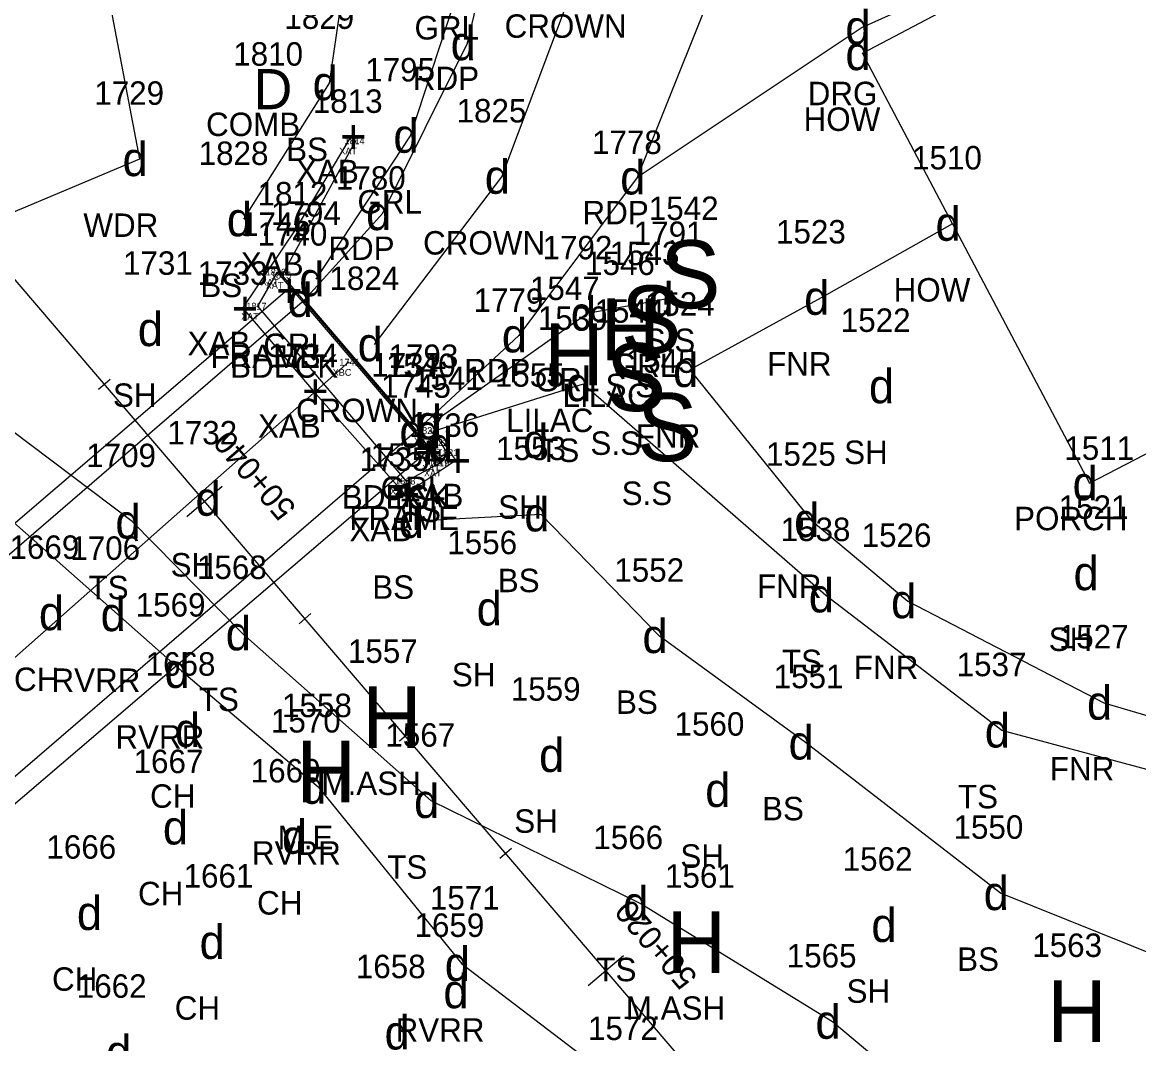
# Model space of a CAD drawing. Extents: x 461160 to 461373, y 202903 to 203086.
# Drawn here: x 461314.15 to 461350.31, y 202961.57 to 202994.66 of the extents above; entities that cross this region are included whole.
import ezdxf

# ---------------------------------------------------------------- set-up
doc = ezdxf.new("R2010")
doc.units = 0
for name, color, linetype in [('Level 11', 7, 'Continuous'), ('Level 12', 7, 'Continuous'), ('Level 13', 7, 'Continuous'), ('Level 14', 7, 'Continuous'), ('Level 15', 7, 'Continuous'), ('Level 17', 7, 'Continuous'), ('Level 34', 7, 'Continuous'), ('Level 35', 7, 'Continuous'), ('Level 37', 7, 'Continuous'), ('Level 46', 7, 'Continuous'), ('Level 47', 7, 'Continuous'), ('Level 48', 7, 'Continuous'), ('Level 49', 7, 'Continuous')]:
    doc.layers.add(name, color=color, linetype=linetype)

msp = doc.modelspace()

# ---------------------------------------------------------------- linework, layer by layer
at = {"layer": 'Level 11'}
for points in [[(461368.16, 202993.988), (461361.614, 202999.669), (461352.956, 203006.007), (461341.424, 203009.197), (461337.518, 203007.355), (461337.431, 203004.112), (461337.186, 202997.424), (461334.068, 202989.63), (461330.234, 202984.513), (461326.916, 202981.421), (461323.296, 202985.661), (461325.835, 202988.474), (461328.575, 202993.98), (461329.756, 202998.988), (461329.989, 203003.994), (461337.431, 203004.112), (461329.989, 203003.994)], [(461337.431, 203004.112), (461339.381, 203001.223), (461342.793, 203002.894), (461345.883, 202999.616), (461347.736, 203000.184), (461348.888, 202997.876), (461341.361, 202994.491), (461334.068, 202989.63)]]:
    msp.add_lwpolyline(points, dxfattribs=at)
at = {"layer": 'Level 12'}
msp.add_line((461346.056, 202948.738), (461294.056, 203009.532), dxfattribs=at)
for points in [[(461323.672, 202986.332), (461326.722, 202990.981), (461328.569, 202996.619), (461329.316, 203001.28), (461328.204, 203004.939)], [(461344.281, 202988.129), (461340.027, 202985.73), (461335.779, 202983.392), (461339.702, 202978.527), (461342.84, 202975.899), (461349.186, 202972.612), (461353.842, 202971.233), (461355.83, 202970.143), (461358.135, 202966.469)], [(461334.989, 202985.682), (461332.465, 202985.218), (461327.476, 202981.698)]]:
    msp.add_lwpolyline(points, dxfattribs=at)
at = {"layer": 'Level 13'}
for points in [[(461344.281, 202988.129), (461341.364, 202993.658), (461347.97, 202997.141), (461350.021, 202998.196), (461353.693, 202991.517), (461352.33, 202990.757), (461354.403, 202986.654)], [(461344.281, 202988.129), (461348.72, 202979.72), (461356.092, 202983.553), (461354.403, 202986.654)], [(461316.616, 202982.772), (461316.996, 202983.097)], [(461319.486, 202978.648), (461320.626, 202979.623)], [(461323.116, 202975.173), (461323.496, 202975.498)], [(461326.366, 202971.373), (461326.746, 202971.698)], [(461329.616, 202967.574), (461329.996, 202967.899)], [(461332.486, 202963.449), (461333.626, 202964.424)]]:
    msp.add_lwpolyline(points, dxfattribs=at)
at = {"layer": 'Level 14'}
msp.add_lwpolyline([(461301.65, 202990.994), (461304.551, 202996.947), (461311.823, 203001.37), (461316.945, 203004), (461316.225, 202999.291), (461317.949, 202990.224), (461310.29, 202987.008), (461301.65, 202990.994)], dxfattribs=at)
at = {"layer": 'Level 17'}
for points in [[(461271.342, 203006.356), (461278.053, 203003.256), (461286.412, 202998.583), (461294.243, 202992.971), (461302.269, 202987.612), (461311.447, 202980.59), (461317.239, 202975.481), (461319.309, 202973.643)], [(461319.309, 202973.643), (461323.731, 202969.886), (461328.385, 202964.15), (461333.938, 202959.923), (461341.989, 202956.284)]]:
    msp.add_lwpolyline(points, dxfattribs=at)
at = {"layer": 'Level 34'}
for points in [[(461326.916, 202981.421), (461313.074, 202969.494), (461299.278, 202957.624), (461295.638, 202961.869), (461309.508, 202973.783), (461323.296, 202985.661), (461326.916, 202981.421)], [(461324.72, 202983.644), (461311.442, 202971.896), (461297.739, 202960.242)]]:
    msp.add_lwpolyline(points, dxfattribs=at)
at = {"layer": 'Level 35'}
for points in [[(461321.296, 202985.391), (461323.019, 202987.964), (461324.808, 202990.962)], [(461324.947, 202990.818), (461322.567, 202986.463), (461322.409, 202986.565), (461321.769, 202985.459), (461326.591, 202979.793), (461327.688, 202980.382), (461327.637, 202980.538), (461327.918, 202980.713), (461327.71, 202981.041), (461327.363, 202981.429)], [(461322.409, 202986.565), (461327.688, 202980.382)], [(461327.637, 202980.538), (461322.567, 202986.463)], [(461321.296, 202985.391), (461323.574, 202982.72), (461326.539, 202979.364), (461328.193, 202980.466), (461327.836, 202980.984)]]:
    msp.add_lwpolyline(points, dxfattribs=at)
at = {"layer": 'Level 37'}
for points in [[(461322.735, 202985.975), (461295.405, 202962.57)], [(461299.888, 202957.36), (461327.236, 202980.731)]]:
    msp.add_lwpolyline(points, dxfattribs=at)
at = {"layer": 'Level 48'}
for points in [[(461321.327, 202988.274), (461324.106, 202992.683), (461325.466, 203002.03), (461321.733, 203002.708), (461316.945, 203004), (461321.225, 203006.69), (461324.085, 203007.39), (461327.398, 203011.243), (461327.047, 203014.732), (461324.41, 203015.108), (461324.41, 203015.108), (461321.477, 203013.865), (461317.057, 203013.221), (461311.718, 203019.474), (461304.97, 203028.576), (461302.488, 203033.292)], [(461321.327, 202988.274), (461324.106, 202992.683), (461325.466, 203002.03), (461321.733, 203002.708), (461316.945, 203004), (461321.225, 203006.69), (461324.085, 203007.39), (461327.398, 203011.243), (461327.047, 203014.732), (461324.41, 203015.108), (461324.41, 203015.108), (461321.477, 203013.865), (461317.057, 203013.221), (461311.718, 203019.474), (461304.97, 203028.576), (461302.488, 203033.292)], [(461321.29, 202974.86), (461317.717, 202978.484), (461312.473, 202982.423), (461305.824, 202987.874), (461301.65, 202990.994), (461300.034, 202993.51), (461304.787, 202998.277), (461312.691, 203003.124), (461318.698, 203006.786), (461322.707, 203009.684), (461325.345, 203012.481), (461324.782, 203012.846), (461322.016, 203009.952), (461316.942, 203006.65), (461311.004, 203002.871), (461303.318, 202997.851), (461297.451, 202992.823)], [(461321.29, 202974.86), (461317.717, 202978.484), (461312.473, 202982.423), (461305.824, 202987.874), (461301.65, 202990.994), (461300.034, 202993.51), (461304.787, 202998.277), (461312.691, 203003.124), (461318.698, 203006.786), (461322.707, 203009.684), (461325.345, 203012.481), (461324.782, 203012.846), (461322.016, 203009.952), (461316.942, 203006.65), (461311.004, 203002.871), (461303.318, 202997.851), (461297.451, 202992.823)], [(461325.564, 202984.223), (461329.682, 202989.652), (461332.323, 202996.674), (461333.208, 203003.38)], [(461357.687, 202965.645), (461352.427, 202969.949), (461345.877, 202971.711), (461340.176, 202976.089), (461332.316, 202982.931), (461327.452, 202981.402), (461327.836, 202980.984)], [(461357.687, 202965.645), (461352.427, 202969.949), (461345.877, 202971.711), (461340.176, 202976.089), (461332.316, 202982.931), (461327.452, 202981.402), (461327.836, 202980.984)], [(461352.229, 202963.871), (461345.84, 202966.444), (461339.521, 202971.322), (461334.79, 202974.771), (461330.961, 202978.713), (461326.896, 202978.498)], [(461352.229, 202963.871), (461345.84, 202966.444), (461339.521, 202971.322), (461334.79, 202974.771), (461330.961, 202978.713), (461326.896, 202978.498)], [(461344.812, 202958.571), (461340.392, 202962.274), (461334.167, 202966.108), (461327.392, 202969.428), (461321.29, 202974.86)], [(461344.812, 202958.571), (461340.392, 202962.274), (461334.167, 202966.108), (461327.392, 202969.428), (461321.29, 202974.86)]]:
    msp.add_lwpolyline(points, dxfattribs=at)

# ---------------------------------------------------------------- texts
at = {"layer": 'Level 13'}
for s, p in [('50+040', (461323.056, 202978.935)), ('50+020', (461336.056, 202963.737))]:
    msp.add_text(s, height=0.75, rotation=130.5419, dxfattribs=at).set_placement(p)
at = {"layer": 'Level 14'}
for s, height, p in [('S', 2.2, (461334.807, 202985.392)), ('S', 2.2, (461333.539, 202983.929)), ('H', 2, (461332.882, 202983.71)), ('H', 2, (461331.056, 202982.9)), ('S', 2.2, (461333.048, 202982.062)), ('S', 2.2, (461334.06, 202980.439)), ('H', 2, (461325.162, 202971.142)), ('H', 2, (461323.028, 202969.384)), ('H', 2, (461335.018, 202963.858)), ('H', 2, (461347.345, 202961.615))]:
    msp.add_text(s, height=height, dxfattribs=at).set_placement(p)
at = {"layer": 'Level 15'}
msp.add_text('D', height=1.3, dxfattribs=at).set_placement((461321.644, 202991.841))
at = {"layer": 'Level 46'}
for s, height, p in [(' GRL  ', 0.76, (461326.574, 202994.099)), (' CROWN  ', 0.76, (461329.493, 202994.154)), (' RDP  ', 0.76, (461326.523, 202992.46)), (' DRG  ', 0.76, (461339.309, 202991.971)), (' HOW  ', 0.76, (461339.177, 202991.138)), (' COMB  ', 0.76, (461319.823, 202990.971)), (' BS  ', 0.76, (461322.416, 202990.163)), (' XAT  ', 0.22, (461324.338, 202990.378)), (' XAB  ', 0.76, (461322.738, 202989.442)), (' GRL  ', 0.76, (461324.727, 202988.461)), (' RDP  ', 0.76, (461332.016, 202988.11)), (' WDR  ', 0.76, (461315.849, 202987.704)), (' CROWN  ', 0.76, (461326.852, 202987.132)), (' RDP  ', 0.76, (461323.783, 202986.954)), (' XAB  ', 0.76, (461320.949, 202986.444)), (' BS  ', 0.76, (461319.637, 202985.754)), (' XAT  ', 0.22, (461321.8, 202986.125)), (' XAT  ', 0.22, (461321.958, 202986.023)), (' HOW  ', 0.76, (461342.094, 202985.609)), (' XAT  ', 0.22, (461321.16, 202985.019)), (' XAB  ', 0.76, (461319.226, 202983.871)), (' GRL  ', 0.76, (461321.677, 202983.812)), (' S.S  ', 0.76, (461334.031, 202983.972)), (' FRAME  ', 0.76, (461319.962, 202983.455)), (' BDECK  ', 0.76, (461320.601, 202983.141)), (' GRL  ', 0.76, (461332.994, 202983.162)), (' FNR  ', 0.76, (461337.993, 202983.21)), (' RDP  ', 0.76, (461328.182, 202982.993)), (' XBC  ', 0.22, (461324.125, 202983.204)), (' GRL  ', 0.76, (461330.47, 202982.698)), (' S.S  ', 0.76, (461332.763, 202982.509)), (' SH  ', 0.76, (461316.808, 202982.196)), (' LILAC  ', 0.76, (461331.369, 202982.19)), (' CROWN  ', 0.76, (461322.734, 202981.703)), (' LILAC  ', 0.76, (461329.543, 202981.38)), (' XAB  ', 0.76, (461321.504, 202981.2)), (' S.S  ', 0.76, (461332.272, 202980.642)), (' FNR  ', 0.76, (461333.745, 202980.872)), (' XAT  ', 0.22, (461326.754, 202980.989)), (' TS  ', 0.76, (461330.614, 202980.411)), (' SH  ', 0.76, (461340.489, 202980.346)), (' XAT  ', 0.22, (461327.101, 202980.601)), (' XAT  ', 0.22, (461327.028, 202980.098)), (' XAT  ', 0.22, (461327.309, 202980.273)), (' GRL  ', 0.76, (461325.481, 202979.178)), (' XAT  ', 0.22, (461327.079, 202979.942)), (' BDECK  ', 0.76, (461324.221, 202978.901)), (' TS  ', 0.76, (461325.75, 202978.882)), (' XAT  ', 0.22, (461325.982, 202979.353)), (' XAB  ', 0.76, (461326.123, 202978.946)), (' S.S  ', 0.76, (461333.284, 202979.019)), (' TS  ', 0.76, (461326.134, 202978.464)), (' SH  ', 0.76, (461329.284, 202978.57)), (' FRAME  ', 0.76, (461324.463, 202978.211)), (' PORCH  ', 0.76, (461345.995, 202978.2)), (' XAB  ', 0.76, (461324.469, 202977.844)), (' SH  ', 0.76, (461318.676, 202976.7)), (' TS  ', 0.76, (461316.015, 202975.964)), (' BS  ', 0.76, (461325.206, 202975.978)), (' BS  ', 0.76, (461329.271, 202976.193)), (' FNR  ', 0.76, (461337.668, 202976.007)), (' SH  ', 0.76, (461347.115, 202974.288)), (' TS  ', 0.76, (461338.474, 202973.569)), (' FNR  ', 0.76, (461340.806, 202973.379)), (' CH  ', 0.76, (461313.604, 202972.992)), (' SH  ', 0.76, (461327.783, 202973.144)), (' RVRR  ', 0.76, (461314.816, 202972.961)), (' TS  ', 0.76, (461319.588, 202972.34)), (' BS  ', 0.76, (461333.1, 202972.251)), (' RVRR  ', 0.76, (461316.886, 202971.123)), (' FNR  ', 0.76, (461347.152, 202970.092)), (' M.ASH  ', 0.76, (461323.562, 202969.622)), (' CH  ', 0.76, (461318.01, 202969.208)), (' TS  ', 0.76, (461344.175, 202969.191)), (' BS  ', 0.76, (461337.831, 202968.802)), (' SH  ', 0.76, (461329.805, 202968.398)), (' M.E  ', 0.76, (461322.14, 202967.864)), (' RVRR  ', 0.76, (461321.308, 202967.366)), (' SH  ', 0.76, (461335.186, 202967.264)), (' TS  ', 0.76, (461325.69, 202966.908)), (' CH  ', 0.76, (461317.62, 202966.05)), (' CH  ', 0.76, (461321.476, 202965.748)), (' BS  ', 0.76, (461344.15, 202963.924)), (' TS  ', 0.76, (461332.465, 202963.588)), (' CH  ', 0.76, (461314.835, 202963.279)), (' SH  ', 0.76, (461340.568, 202962.889)), (' CH  ', 0.76, (461318.808, 202962.342)), (' M.ASH  ', 0.76, (461333.418, 202962.338)), (' RVRR  ', 0.76, (461325.962, 202961.63))]:
    msp.add_text(s, height=height, dxfattribs=at).set_placement(p)
at = {"layer": 'Level 47'}
for s, height, p in [('d', 1.1, (461340.811, 202993.941)), ('d', 1.1, (461328.025, 202993.43)), ('d', 1.1, (461340.814, 202993.108)), ('d', 1.1, (461323.556, 202992.133)), ('d', 1.1, (461326.172, 202990.431)), ('+', 1.1, (461324.449, 202990.412)), ('d', 1.1, (461317.399, 202989.674)), ('+', 0.15, (461324.898, 202990.743)), ('d', 1.1, (461329.132, 202989.102)), ('d', 1.1, (461333.518, 202989.08)), ('d', 1.1, (461325.285, 202987.924)), ('d', 1.1, (461320.777, 202987.724)), ('d', 1.1, (461343.731, 202987.579)), ('+', 1.1, (461322.66, 202987.414)), ('d', 1.1, (461323.122, 202985.782)), ('+', 0.15, (461322.36, 202986.49)), ('+', 0.15, (461322.518, 202986.388)), ('+', 1.1, (461322.376, 202985.425)), ('d', 1.1, (461322.746, 202985.111)), ('d', 1.1, (461334.439, 202985.132)), ('d', 1.1, (461339.477, 202985.18)), ('+', 1.1, (461320.937, 202984.841)), ('d', 1.1, (461331.915, 202984.668)), ('d', 1.1, (461317.894, 202984.166)), ('+', 0.15, (461321.72, 202985.384)), ('d', 1.1, (461329.684, 202983.963)), ('d', 1.1, (461325.014, 202983.673)), ('d', 1.1, (461335.229, 202982.842)), ('+', 0.15, (461324.671, 202983.569)), ('d', 1.1, (461331.766, 202982.381)), ('d', 1.1, (461341.575, 202982.316)), ('+', 1.1, (461323.215, 202982.17)), ('d', 1.1, (461326.926, 202981.148)), ('d', 1.1, (461326.366, 202980.871)), ('d', 1.1, (461326.902, 202980.852)), ('d', 1.1, (461330.37, 202980.54)), ('+', 0.15, (461327.314, 202981.354)), ('d', 1.1, (461327.286, 202980.434)), ('+', 1.1, (461326.877, 202980.181)), ('+', 0.15, (461327.661, 202980.966)), ('+', 0.15, (461327.869, 202980.638)), ('+', 1.1, (461327.834, 202979.916)), ('+', 0.15, (461327.588, 202980.463)), ('+', 0.15, (461327.639, 202980.307)), ('d', 1.1, (461348.17, 202979.17)), ('d', 1.1, (461319.762, 202978.67)), ('+', 1.1, (461326.18, 202978.814)), ('+', 0.15, (461326.542, 202979.718)), ('d', 1.1, (461330.411, 202978.163)), ('d', 1.1, (461317.167, 202977.934)), ('d', 1.1, (461326.346, 202977.948)), ('d', 1.1, (461339.152, 202977.977)), ('d', 1.1, (461348.201, 202976.258)), ('d', 1.1, (461339.626, 202975.539)), ('d', 1.1, (461328.869, 202975.114)), ('d', 1.1, (461342.29, 202975.349)), ('d', 1.1, (461314.69, 202974.962)), ('d', 1.1, (461316.689, 202974.931)), ('d', 1.1, (461320.74, 202974.31)), ('d', 1.1, (461334.24, 202974.221)), ('d', 1.1, (461318.759, 202973.093)), ('d', 1.1, (461348.636, 202972.062)), ('d', 1.1, (461319.096, 202971.178)), ('d', 1.1, (461345.327, 202971.161)), ('d', 1.1, (461338.971, 202970.772)), ('d', 1.1, (461330.891, 202970.368)), ('d', 1.1, (461323.181, 202969.336)), ('d', 1.1, (461336.272, 202969.234)), ('d', 1.1, (461326.842, 202968.878)), ('d', 1.1, (461318.706, 202968.02)), ('d', 1.1, (461322.562, 202967.718)), ('d', 1.1, (461345.29, 202965.894)), ('d', 1.1, (461333.617, 202965.558)), ('d', 1.1, (461315.921, 202965.249)), ('d', 1.1, (461341.654, 202964.859)), ('d', 1.1, (461319.894, 202964.312)), ('d', 1.1, (461327.835, 202963.6)), ('d', 1.1, (461327.79, 202962.714)), ('d', 1.1, (461339.842, 202961.724)), ('d', 1.1, (461325.886, 202961.377)), ('d', 1.1, (461316.865, 202960.742))]:
    msp.add_text(s, height=height, dxfattribs=at).set_placement(p)
at = {"layer": 'Level 49'}
for s, height, p in [(' 1829 ', 0.76, (461322.359, 202994.443)), (' 1810 ', 0.76, (461320.703, 202993.251)), (' 1795 ', 0.76, (461324.978, 202992.741)), (' 1729 ', 0.76, (461316.202, 202991.984)), (' 1813 ', 0.76, (461323.28, 202991.722)), (' 1825 ', 0.76, (461327.938, 202991.412)), (' 1778 ', 0.76, (461332.324, 202990.39)), (' 1828 ', 0.76, (461319.583, 202990.034)), (' 1814 ', 0.22, (461324.505, 202990.708)), (' 1510 ', 0.76, (461342.69, 202989.889)), (' 1780 ', 0.76, (461324.028, 202989.234)), (' 1812 ', 0.76, (461321.491, 202988.724)), (' 1542 ', 0.76, (461334.163, 202988.252)), (' 1794 ', 0.76, (461321.928, 202988.092)), (' 1746 ', 0.76, (461320.952, 202987.735)), (' 1791 ', 0.76, (461333.676, 202987.442)), (' 1523 ', 0.76, (461338.283, 202987.49)), (' 1740 ', 0.76, (461321.489, 202987.421)), (' 1792 ', 0.76, (461330.721, 202986.978)), (' 1543 ', 0.76, (461332.895, 202986.789)), (' 1731 ', 0.76, (461317.131, 202986.476)), (' 1546 ', 0.76, (461332.099, 202986.47)), (' 1733 ', 0.76, (461319.552, 202986.151)), (' 1824 ', 0.76, (461323.82, 202985.983)), (' 1816 ', 0.22, (461321.956, 202986.455)), (' 1815 ', 0.22, (461322.125, 202986.353)), (' 1547 ', 0.76, (461330.312, 202985.66)), (' 1779 ', 0.76, (461328.487, 202985.273)), (' 1544 ', 0.76, (461332.404, 202984.922)), (' 1524 ', 0.76, (461334.035, 202985.152)), (' 1817 ', 0.22, (461321.327, 202985.349)), (' 1539 ', 0.76, (461330.569, 202984.691)), (' 1522 ', 0.76, (461340.381, 202984.626)), (' 1734 ', 0.76, (461321.83, 202983.48)), (' 1793 ', 0.76, (461325.732, 202983.458)), (' 1737 ', 0.76, (461325.172, 202983.181)), (' 1540 ', 0.76, (461325.645, 202983.162)), (' 1545 ', 0.76, (461333.416, 202983.299)), (' 1741 ', 0.22, (461324.34, 202983.534)), (' 1541 ', 0.76, (461326.523, 202982.744)), (' 1555 ', 0.76, (461329.176, 202982.85)), (' 1745 ', 0.76, (461325.492, 202982.491)), (' 1732 ', 0.76, (461318.568, 202980.98)), (' 1736 ', 0.76, (461326.41, 202981.226)), (' 1823 ', 0.22, (461326.859, 202981.319)), (' 1709 ', 0.76, (461315.94, 202980.244)), (' 1554 ', 0.76, (461325.152, 202980.258)), (' 1822 ', 0.22, (461327.206, 202980.931)), (' 1553 ', 0.76, (461329.217, 202980.473)), (' 1525 ', 0.76, (461337.958, 202980.287)), (' 1511 ', 0.76, (461347.622, 202980.48)), (' 1735 ', 0.76, (461324.795, 202980.124)), (' 1820 ', 0.22, (461327.114, 202980.428)), (' 1821 ', 0.22, (461327.538, 202980.603)), (' 1819 ', 0.22, (461327.245, 202980.272)), (' 1818 ', 0.22, (461326.149, 202979.683)), (' 1521 ', 0.76, (461347.438, 202978.568)), (' 1538 ', 0.76, (461338.432, 202977.849)), (' 1526 ', 0.76, (461341.057, 202977.659)), (' 1556 ', 0.76, (461327.636, 202977.424)), (' 1669 ', 0.76, (461313.457, 202977.272)), (' 1706 ', 0.76, (461315.426, 202977.241)), (' 1568 ', 0.76, (461319.528, 202976.62)), (' 1552 ', 0.76, (461333.046, 202976.531)), (' 1569 ', 0.76, (461317.544, 202975.403)), (' 1527 ', 0.76, (461347.442, 202974.372)), (' 1557 ', 0.76, (461324.418, 202973.902)), (' 1668 ', 0.76, (461317.866, 202973.488)), (' 1537 ', 0.76, (461344.133, 202973.471)), (' 1551 ', 0.76, (461338.208, 202973.082)), (' 1559 ', 0.76, (461329.694, 202972.678)), (' 1558 ', 0.76, (461322.284, 202972.144)), (' 1570 ', 0.76, (461321.924, 202971.646)), (' 1560 ', 0.76, (461334.997, 202971.544)), (' 1567 ', 0.76, (461325.63, 202971.188)), (' 1667 ', 0.76, (461317.476, 202970.33)), (' 1660 ', 0.76, (461321.269, 202970.028)), (' 1550 ', 0.76, (461344.033, 202968.204)), (' 1666 ', 0.76, (461314.652, 202967.559)), (' 1566 ', 0.76, (461332.366, 202967.868)), (' 1562 ', 0.76, (461340.442, 202967.169)), (' 1661 ', 0.76, (461319.095, 202966.622)), (' 1561 ', 0.76, (461334.687, 202966.618)), (' 1571 ', 0.76, (461327.072, 202965.91)), (' 1659 ', 0.76, (461326.575, 202965.024)), (' 1563 ', 0.76, (461346.583, 202964.375)), (' 1565 ', 0.76, (461338.63, 202964.034)), (' 1658 ', 0.76, (461324.674, 202963.687)), (' 1662 ', 0.76, (461315.635, 202963.052)), (' 1572 ', 0.76, (461332.194, 202961.683))]:
    msp.add_text(s, height=height, dxfattribs=at).set_placement(p)

doc.saveas('drawing.dxf')
